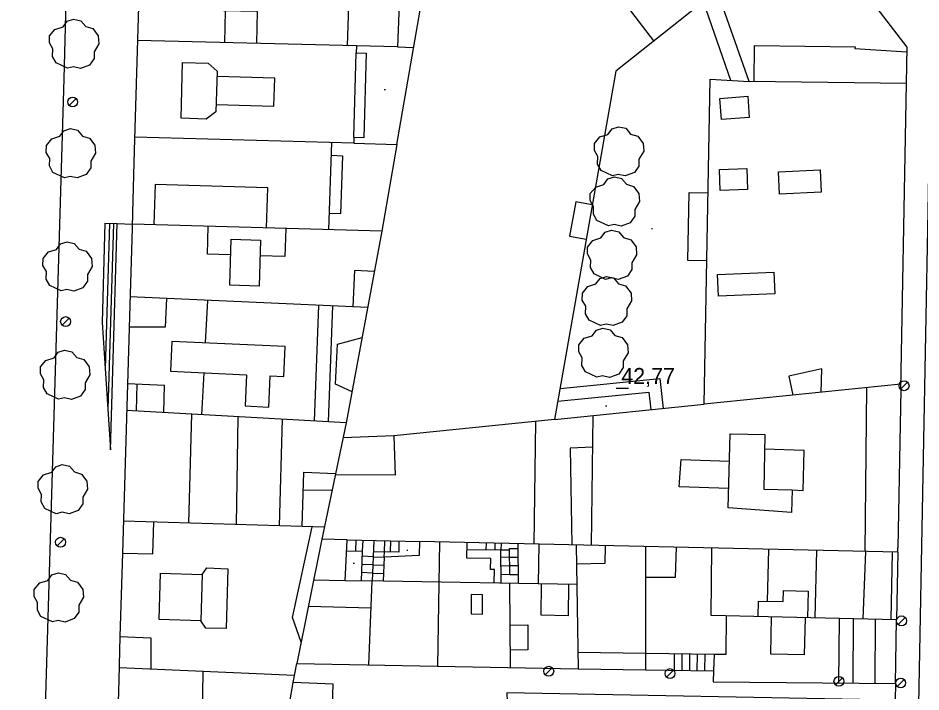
# Model space of a CAD drawing. Extents: x 431390 to 432653, y 4586754 to 4589600.
# Drawn here: x 431558.1 to 431631.4, y 4586887.9 to 4586942.6 of the extents above; entities that cross this region are included whole.
import ezdxf

# ---------------------------------------------------------------- set-up
doc = ezdxf.new("R2010")
doc.units = 0
for name, color, linetype in [('COM_13ES_LN', 7, 'Continuous'), ('COM_17LS_LN', 7, 'Continuous'), ('CON_01_LN', 7, 'Continuous'), ('CON_01FI_LN', 7, 'Continuous'), ('CON_03_LN', 7, 'Continuous'), ('CON_04_LN', 7, 'Continuous'), ('CON_07_LN', 7, 'Continuous'), ('CON_08_LN', 7, 'Continuous'), ('CON_15_LN', 7, 'Continuous'), ('CON_16_LN', 7, 'Continuous'), ('CON_19_LN', 7, 'Continuous'), ('CON_23_LN', 7, 'Continuous'), ('CON_29_LN', 7, 'Continuous'), ('ENE_06_PT', 7, 'Continuous'), ('ENE_08_LN', 7, 'Continuous'), ('ORO_03_PT', 7, 'Continuous'), ('ORO_04_PT', 7, 'Continuous'), ('ORO_04_TX', 7, 'Continuous'), ('VEG_03_PT', 7, 'Continuous')]:
    doc.layers.add(name, color=color, linetype=linetype)

msp = doc.modelspace()

# ---------------------------------------------------------------- linework, layer by layer
at = {"layer": 'COM_13ES_LN'}
for points in [[(431602.09, 4586912.527), (431610.17, 4586913.33), (431610.443, 4586910.91)], [(431601.911, 4586911.504), (431609.287, 4586912.237), (431609.448, 4586910.809)]]:
    msp.add_lwpolyline(points, dxfattribs=at)
at = {"layer": 'COM_17LS_LN'}
for points in [[(431557.318, 4586855.51), (431557.323, 4586855.702), (431559.44, 4586855.68), (431561.861, 4586937.649), (431562.206, 4586950.278), (431562.892, 4586975.427), (431562.96, 4586977.917), (431562.964, 4586978.068), (431563.607, 4587001.597), (431564.129, 4587020.727), (431564.211, 4587023.718), (431562.021, 4587023.778), (431562.213, 4587030.81)], [(431638.056, 4586933.587), (431637.559, 4586906.789), (431637.134, 4586883.917), (431636.702, 4586860.64), (431636.688, 4586859.878), (431630.69, 4586859.99), (431630.704, 4586860.75), (431631.136, 4586884.029), (431631.561, 4586906.901), (431631.932, 4586926.91), (431632.154, 4586938.86), (431632.209, 4586941.8), (431632.22, 4586942.4), (431632.187, 4586942.896)]]:
    msp.add_lwpolyline(points, dxfattribs=at)
at = {"layer": 'CON_01_LN'}
for points in [[(431606.16, 4586969.34), (431584.53, 4586970.044), (431569.734, 4586970.525), (431568.703, 4586970.559), (431568.404, 4586960.429), (431568.304, 4586957.039), (431567.56, 4586931.837), (431567.411, 4586926.808), (431567.374, 4586925.539), (431567.216, 4586920.177), (431566.596, 4586899.166)], [(431629.72, 4586912.441), (431630.23, 4586940.21), (431607.896, 4586969.283)], [(431629.72, 4586912.441), (431629.485, 4586899.612)], [(431629.478, 4586899.241), (431629.485, 4586899.612)], [(431566.596, 4586899.166), (431566.396, 4586892.411)], [(431629.478, 4586899.241), (431629.378, 4586893.771)], [(431629.283, 4586888.601), (431629.378, 4586893.771)], [(431566.396, 4586892.411), (431566.293, 4586888.909)], [(431566.293, 4586888.909), (431565.271, 4586854.269), (431571.972, 4586854.071)]]:
    msp.add_lwpolyline(points, dxfattribs=at)
at = {"layer": 'CON_01FI_LN'}
for points in [[(431585.553, 4586939.762), (431586.359, 4586939.74), (431586.172, 4586932.863), (431585.366, 4586932.885), (431585.354, 4586932.427), (431588.856, 4586932.332), (431591.761, 4586949.172), (431589.269, 4586949.253), (431588.9, 4586940.23), (431585.568, 4586940.313), (431585.553, 4586939.762)], [(431613.786, 4586911.25), (431614.26, 4586937.62), (431617.43, 4586937.44), (431614.833, 4586944.807), (431606.6, 4586938.27), (431601.65, 4586910.016), (431613.786, 4586911.25)], [(431590.691, 4586900.116), (431590.67, 4586898.99), (431587.829, 4586898.844), (431587.75, 4586896.886), (431584.667, 4586896.934), (431584.823, 4586900.249), (431590.691, 4586900.116)], [(431629.258, 4586887.249), (431597.76, 4586887.85), (431597.82, 4586886.43), (431583.634, 4586886.883), (431583.69, 4586888.54), (431580.455, 4586888.677), (431580.737, 4586890.231), (431603.548, 4586889.792), (431614.538, 4586889.618), (431614.51, 4586888.74), (431629.283, 4586888.601)]]:
    msp.add_lwpolyline(points, dxfattribs=at)
at = {"layer": 'CON_03_LN'}
for points in [[(431585.568, 4586940.313), (431567.823, 4586940.757)], [(431585.354, 4586932.427), (431567.592, 4586932.91)], [(431588.856, 4586932.332), (431587.64, 4586925.28), (431584.75, 4586909.73), (431582.74, 4586900.16), (431580.737, 4586890.231)], [(431587.64, 4586925.28), (431567.384, 4586925.869)], [(431586.49, 4586919.094), (431567.21, 4586919.959)], [(431629.728, 4586912.87), (431613.786, 4586911.25)], [(431584.75, 4586909.73), (431566.938, 4586910.754)], [(431601.65, 4586910.016), (431588.6, 4586908.69), (431584.498, 4586908.53)], [(431582.978, 4586901.291), (431566.673, 4586901.762)], [(431584.823, 4586900.249), (431582.768, 4586900.295)], [(431629.478, 4586899.241), (431590.691, 4586900.116)], [(431592.179, 4586890.011), (431592.33, 4586900.079)], [(431603.383, 4586899.83), (431603.548, 4586889.792)], [(431609.038, 4586889.705), (431609.044, 4586899.702)], [(431629.378, 4586893.771), (431614.35, 4586894.11), (431614.391, 4586899.581)], [(431586.577, 4586890.119), (431586.85, 4586896.9)], [(431598.061, 4586889.898), (431598.013, 4586896.726)], [(431615.547, 4586894.083), (431615.52, 4586890.96), (431614.58, 4586890.96), (431614.538, 4586889.618)], [(431580.559, 4586889.248), (431566.322, 4586889.88)], [(431574.158, 4586854.006), (431574.46, 4586872.98), (431575.4, 4586875.46), (431578.98, 4586875.44), (431580.51, 4586877.28), (431580.65, 4586883.4), (431579.55, 4586883.49), (431580.455, 4586888.677)]]:
    msp.add_lwpolyline(points, dxfattribs=at)
at = {"layer": 'CON_04_LN'}
for points in [[(431609.685, 4586940.72), (431598.38, 4586955.48), (431592.856, 4586955.684)], [(431577.492, 4586940.515), (431577.557, 4586943.1), (431574.807, 4586943.169), (431574.896, 4586946.709), (431577.66, 4586946.64), (431577.735, 4586949.629)], [(431584.841, 4586940.331), (431585.159, 4586949.387)], [(431574.897, 4586940.58), (431574.962, 4586943.165)], [(431585.366, 4586932.885), (431585.553, 4586939.762)], [(431571.482, 4586938.971), (431573.548, 4586938.909), (431574.28, 4586938.262), (431574.183, 4586934.971), (431573.389, 4586934.388), (431571.349, 4586934.448), (431571.482, 4586938.971)], [(431574.2, 4586935.557), (431578.883, 4586935.419), (431578.95, 4586937.706), (431574.268, 4586937.844)], [(431630.176, 4586937.27), (431617.43, 4586937.44)], [(431583.348, 4586925.405), (431583.582, 4586932.475)], [(431583.548, 4586931.443), (431584.447, 4586931.413), (431584.292, 4586926.695), (431583.392, 4586926.725)], [(431578.289, 4586925.552), (431578.384, 4586928.813), (431569.25, 4586929.079), (431569.155, 4586925.818)], [(431604.702, 4586927.439), (431603.356, 4586927.675), (431602.866, 4586924.876), (431604.212, 4586924.64)], [(431575.373, 4586923.366), (431573.49, 4586923.421), (431573.556, 4586925.69)], [(431579.843, 4586925.507), (431579.777, 4586923.238), (431577.747, 4586923.297)], [(431577.784, 4586924.57), (431577.675, 4586920.829), (431575.301, 4586920.898), (431575.41, 4586924.639), (431577.784, 4586924.57)], [(431587.036, 4586922.028), (431585.41, 4586922.1), (431585.272, 4586919.149)], [(431570.168, 4586919.826), (431570.06, 4586917.5), (431567.137, 4586917.503)], [(431573.347, 4586916.221), (431573.531, 4586919.675)], [(431582.166, 4586909.879), (431582.514, 4586919.272)], [(431583.296, 4586909.814), (431583.655, 4586919.221)], [(431570.49, 4586913.923), (431576.663, 4586913.65), (431576.551, 4586911.112), (431578.479, 4586911.027), (431578.59, 4586913.544), (431579.685, 4586913.496), (431579.793, 4586915.936), (431570.597, 4586916.343), (431570.49, 4586913.923)], [(431585.221, 4586912.263), (431583.89, 4586912.87), (431584.05, 4586916.12), (431586.04, 4586916.671)], [(431573.036, 4586910.403), (431573.217, 4586913.802)], [(431623.252, 4586912.212), (431623.33, 4586914.12), (431620.65, 4586913.54), (431620.957, 4586911.979)], [(431569.963, 4586910.58), (431570.01, 4586912.77), (431567.002, 4586912.912)], [(431567.776, 4586912.875), (431567.72, 4586910.709)], [(431626.842, 4586899.3), (431626.958, 4586912.589)], [(431575.946, 4586910.236), (431575.808, 4586901.498)], [(431599.991, 4586899.906), (431600.115, 4586909.86)], [(431604.631, 4586899.802), (431604.786, 4586910.335)], [(431588.6, 4586908.69), (431588.71, 4586905.51), (431583.864, 4586905.512)], [(431615.73, 4586902.841), (431615.87, 4586908.85), (431618.707, 4586908.784), (431618.604, 4586904.37), (431620.901, 4586904.317), (431620.858, 4586902.458), (431615.73, 4586902.841)], [(431604.748, 4586907.76), (431602.92, 4586907.7), (431603.047, 4586899.837)], [(431620.901, 4586904.317), (431621.81, 4586904.25), (431621.89, 4586907.5), (431618.68, 4586907.608)], [(431615.767, 4586904.422), (431611.74, 4586904.56), (431611.92, 4586906.76), (431615.818, 4586906.633)], [(431581.171, 4586901.343), (431581.32, 4586905.73), (431583.887, 4586905.621)], [(431583.597, 4586904.242), (431581.271, 4586904.283)], [(431566.596, 4586899.166), (431569.05, 4586899.13), (431569.151, 4586901.69)], [(431581.083, 4586891.945), (431580.4, 4586893.96), (431581.981, 4586901.32)], [(431596.755, 4586896.745), (431596.772, 4586897.839), (431596.458, 4586897.844), (431596.472, 4586898.725), (431594.525, 4586898.755), (431594.545, 4586900.029)], [(431598.713, 4586896.715), (431598.69, 4586899.936)], [(431600.352, 4586896.689), (431600.402, 4586899.897)], [(431605.754, 4586899.776), (431605.72, 4586898.32), (431603.408, 4586898.29)], [(431611.493, 4586899.647), (431611.41, 4586897.21), (431609.042, 4586897.2)], [(431597.313, 4586896.737), (431597.294, 4586899.421), (431594.536, 4586899.451)], [(431618.917, 4586895.272), (431619.012, 4586899.477)], [(431622.765, 4586893.92), (431622.904, 4586899.389)], [(431626.657, 4586893.832), (431626.876, 4586899.3)], [(431628.935, 4586893.781), (431629.04, 4586899.251)], [(431573.062, 4586897.439), (431573.44, 4586897.98), (431575.15, 4586897.89), (431575, 4586893.05), (431573.36, 4586893.1), (431572.954, 4586893.693), (431569.58, 4586893.79), (431569.688, 4586897.536), (431573.062, 4586897.439), (431572.954, 4586893.693)], [(431584.667, 4586896.934), (431582.097, 4586896.974)], [(431603.435, 4586896.641), (431587.75, 4586896.886)], [(431602.78, 4586896.651), (431602.74, 4586894.1), (431600.544, 4586894.135), (431600.584, 4586896.686)], [(431618.162, 4586894.024), (431618.191, 4586895.288), (431620.175, 4586895.243), (431620.195, 4586896.135), (431622.203, 4586896.09), (431622.154, 4586893.934)], [(431594.867, 4586894.247), (431595.785, 4586894.233), (431595.808, 4586895.793), (431594.89, 4586895.807), (431594.867, 4586894.247)], [(431586.762, 4586894.705), (431581.667, 4586894.843)], [(431621.964, 4586893.938), (431621.896, 4586890.92), (431619.179, 4586890.981), (431619.247, 4586894)], [(431624.69, 4586888.644), (431624.739, 4586893.876)], [(431625.849, 4586888.633), (431625.898, 4586893.85)], [(431627.63, 4586888.617), (431627.679, 4586893.809)], [(431598.037, 4586893.335), (431599.473, 4586893.345), (431599.487, 4586891.323), (431598.051, 4586891.313)], [(431566.396, 4586892.411), (431568.91, 4586892.29), (431568.892, 4586889.766)], [(431614.58, 4586890.96), (431603.526, 4586891.102)], [(431572.862, 4586871.352), (431573.151, 4586889.577)]]:
    msp.add_lwpolyline(points, dxfattribs=at)
at = {"layer": 'CON_07_LN'}
msp.add_lwpolyline([(431613.995, 4586922.889), (431612.453, 4586922.917), (431612.552, 4586928.422), (431614.094, 4586928.394)], dxfattribs=at)
at = {"layer": 'CON_08_LN'}
msp.add_lwpolyline([(431613.705, 4586943.911), (431615.915, 4586937.526)], dxfattribs=at)
at = {"layer": 'CON_15_LN'}
msp.add_lwpolyline([(431565.184, 4586925.933), (431566.184, 4586925.904), (431567.384, 4586925.869)], dxfattribs=at)
at = {"layer": 'CON_16_LN'}
for points in [[(431588.9, 4586940.23), (431590.209, 4586940.177)], [(431598.008, 4586897.429), (431597.993, 4586899.54)]]:
    msp.add_lwpolyline(points, dxfattribs=at)
at = {"layer": 'CON_19_LN'}
msp.add_lwpolyline([(431629.283, 4586888.601), (431629.258, 4586887.249)], dxfattribs=at)
at = {"layer": 'CON_23_LN'}
for points in [[(431565.184, 4586925.933), (431564.947, 4586917.873), (431565.197, 4586914.156), (431565.42, 4586910.849), (431565.643, 4586907.541), (431566.184, 4586925.904)], [(431565.544, 4586925.923), (431565.197, 4586914.156)], [(431565.864, 4586925.913), (431565.42, 4586910.849)], [(431585.513, 4586900.233), (431585.492, 4586899.334)], [(431586.083, 4586900.22), (431586.047, 4586899.321)], [(431586.983, 4586900.2), (431586.85, 4586896.9)], [(431587.846, 4586899.28), (431587.883, 4586900.18)], [(431589.023, 4586900.154), (431589.003, 4586899.254), (431587.846, 4586899.28)], [(431588.343, 4586900.169), (431588.323, 4586899.269)], [(431596.082, 4586899.994), (431596.069, 4586899.433)], [(431596.802, 4586899.978), (431596.79, 4586899.426)], [(431597.306, 4586899.967), (431597.294, 4586899.421)], [(431597.993, 4586899.54), (431598.693, 4586899.545)], [(431584.781, 4586899.35), (431586.047, 4586899.321)], [(431586.047, 4586899.321), (431585.95, 4586896.914)], [(431586.93, 4586898.88), (431586.031, 4586898.916)], [(431586.93, 4586898.88), (431587.829, 4586898.844)], [(431586.947, 4586899.3), (431587.846, 4586899.28)], [(431587.829, 4586898.844), (431587.846, 4586899.28)], [(431597.994, 4586899.426), (431597.294, 4586899.421)], [(431597.998, 4586898.837), (431597.298, 4586898.832)], [(431597.998, 4586898.836), (431598.698, 4586898.841)], [(431586.903, 4586898.22), (431586.004, 4586898.256)], [(431586.903, 4586898.22), (431587.802, 4586898.184)], [(431598.703, 4586898.138), (431598.003, 4586898.133), (431597.303, 4586898.128)], [(431586.877, 4586897.56), (431585.977, 4586897.596)], [(431586.877, 4586897.56), (431587.776, 4586897.524)], [(431598.008, 4586897.43), (431597.308, 4586897.425)], [(431598.008, 4586897.429), (431598.708, 4586897.434)], [(431611.348, 4586891.002), (431611.331, 4586889.669)], [(431611.969, 4586890.994), (431611.952, 4586889.659)], [(431612.59, 4586890.986), (431612.573, 4586889.649)], [(431613.21, 4586890.978), (431613.193, 4586889.639)], [(431613.831, 4586890.97), (431613.814, 4586889.629)]]:
    msp.add_lwpolyline(points, dxfattribs=at)
at = {"layer": 'CON_29_LN'}
for points in [[(431572.195, 4586910.452), (431571.949, 4586901.61)], [(431579.543, 4586910.029), (431579.318, 4586901.397)]]:
    msp.add_lwpolyline(points, dxfattribs=at)
at = {"layer": 'ENE_06_PT'}
for p, q in [((431562.842, 4586936.052), (431562.276, 4586935.486)), ((431562.272, 4586918.242), (431561.706, 4586917.676)), ((431630.272, 4586913.032), (431629.706, 4586912.466)), ((431561.862, 4586900.342), (431561.296, 4586899.776)), ((431630.062, 4586893.962), (431629.496, 4586893.396)), ((431601.455, 4586889.876), (431600.889, 4586889.31)), ((431611.287, 4586889.686), (431610.721, 4586889.12)), ((431624.984, 4586889.052), (431624.418, 4586888.486)), ((431629.991, 4586888.922), (431629.425, 4586888.356))]:
    msp.add_line(p, q, dxfattribs=at)
for centre in [(431562.559, 4586935.769), (431561.989, 4586917.959), (431629.989, 4586912.749), (431561.579, 4586900.059), (431629.779, 4586893.679), (431601.172, 4586889.593), (431611.004, 4586889.403), (431624.701, 4586888.769), (431629.708, 4586888.639)]:
    msp.add_circle(centre, 0.4, dxfattribs=at)
at = {"layer": 'ENE_08_LN'}
for points in [[(431617.829, 4586937.435), (431617.869, 4586940.342), (431626.01, 4586940.23), (431626.002, 4586940.1), (431630.223, 4586939.838)], [(431617.434, 4586934.503), (431615.18, 4586934.34), (431615.055, 4586936.065), (431617.309, 4586936.228), (431617.434, 4586934.503)], [(431617.294, 4586928.661), (431615.08, 4586928.59), (431615.025, 4586930.299), (431617.239, 4586930.37), (431617.294, 4586928.661)], [(431623.255, 4586928.463), (431619.88, 4586928.3), (431619.793, 4586930.102), (431623.168, 4586930.265), (431623.255, 4586928.463)], [(431619.506, 4586920.21), (431614.93, 4586920.01), (431614.853, 4586921.764), (431619.429, 4586921.964), (431619.506, 4586920.21)]]:
    msp.add_lwpolyline(points, dxfattribs=at)
at = {"layer": 'ORO_03_PT'}
for p, q in [((431587.83, 4586936.79), (431587.93, 4586936.79)), ((431609.49, 4586925.5), (431609.59, 4586925.5)), ((431605.78, 4586911.11), (431605.88, 4586911.11)), ((431589.65, 4586899.42), (431589.75, 4586899.42)), ((431585.31, 4586898.35), (431585.41, 4586898.35))]:
    msp.add_line(p, q, dxfattribs=at)
at = {"layer": 'ORO_04_PT'}
msp.add_line((431606.63, 4586912.55), (431607.63, 4586912.55), dxfattribs=at)
at = {"layer": 'VEG_03_PT'}
for points in [[(431562.154, 4586938.501), (431561.227, 4586938.936), (431560.939, 4586939.457), (431560.962, 4586940.071), (431560.68, 4586940.563), (431560.688, 4586941.126), (431561.129, 4586941.661), (431561.782, 4586941.865), (431562.117, 4586942.316), (431562.643, 4586942.486), (431563.223, 4586942.353), (431563.623, 4586941.887), (431564.197, 4586941.717), (431564.631, 4586941.134), (431564.68, 4586940.492), (431564.297, 4586939.845), (431564.297, 4586939.295), (431563.925, 4586938.761), (431563.186, 4586938.486), (431562.621, 4586938.614), (431562.154, 4586938.501)], [(431561.894, 4586929.621), (431560.967, 4586930.056), (431560.679, 4586930.577), (431560.702, 4586931.191), (431560.42, 4586931.683), (431560.428, 4586932.246), (431560.869, 4586932.781), (431561.522, 4586932.985), (431561.857, 4586933.436), (431562.383, 4586933.606), (431562.963, 4586933.473), (431563.363, 4586933.007), (431563.937, 4586932.837), (431564.371, 4586932.254), (431564.42, 4586931.612), (431564.037, 4586930.965), (431564.037, 4586930.415), (431563.665, 4586929.881), (431562.926, 4586929.606), (431562.361, 4586929.734), (431561.894, 4586929.621)], [(431606.344, 4586929.781), (431605.417, 4586930.216), (431605.129, 4586930.737), (431605.152, 4586931.351), (431604.87, 4586931.843), (431604.878, 4586932.406), (431605.319, 4586932.941), (431605.972, 4586933.145), (431606.307, 4586933.596), (431606.833, 4586933.766), (431607.413, 4586933.633), (431607.813, 4586933.167), (431608.387, 4586932.997), (431608.821, 4586932.414), (431608.87, 4586931.772), (431608.487, 4586931.125), (431608.487, 4586930.575), (431608.115, 4586930.041), (431607.376, 4586929.766), (431606.811, 4586929.894), (431606.344, 4586929.781)], [(431606.004, 4586925.711), (431605.077, 4586926.146), (431604.789, 4586926.667), (431604.812, 4586927.281), (431604.53, 4586927.773), (431604.538, 4586928.336), (431604.979, 4586928.871), (431605.632, 4586929.075), (431605.967, 4586929.526), (431606.493, 4586929.696), (431607.073, 4586929.563), (431607.473, 4586929.097), (431608.047, 4586928.927), (431608.481, 4586928.344), (431608.53, 4586927.702), (431608.147, 4586927.055), (431608.147, 4586926.505), (431607.775, 4586925.971), (431607.036, 4586925.696), (431606.471, 4586925.824), (431606.004, 4586925.711)], [(431605.774, 4586921.381), (431604.847, 4586921.816), (431604.559, 4586922.337), (431604.582, 4586922.951), (431604.3, 4586923.443), (431604.308, 4586924.006), (431604.749, 4586924.541), (431605.402, 4586924.745), (431605.737, 4586925.196), (431606.263, 4586925.366), (431606.843, 4586925.233), (431607.243, 4586924.767), (431607.817, 4586924.597), (431608.251, 4586924.014), (431608.3, 4586923.372), (431607.917, 4586922.725), (431607.917, 4586922.175), (431607.545, 4586921.641), (431606.806, 4586921.366), (431606.241, 4586921.494), (431605.774, 4586921.381)], [(431561.624, 4586920.441), (431560.697, 4586920.876), (431560.409, 4586921.397), (431560.432, 4586922.011), (431560.15, 4586922.503), (431560.158, 4586923.066), (431560.599, 4586923.601), (431561.252, 4586923.805), (431561.587, 4586924.256), (431562.113, 4586924.426), (431562.693, 4586924.293), (431563.093, 4586923.827), (431563.667, 4586923.657), (431564.101, 4586923.074), (431564.15, 4586922.432), (431563.767, 4586921.785), (431563.767, 4586921.235), (431563.395, 4586920.701), (431562.656, 4586920.426), (431562.091, 4586920.554), (431561.624, 4586920.441)], [(431605.364, 4586917.641), (431604.437, 4586918.076), (431604.149, 4586918.597), (431604.172, 4586919.211), (431603.89, 4586919.703), (431603.898, 4586920.266), (431604.339, 4586920.801), (431604.992, 4586921.005), (431605.327, 4586921.456), (431605.853, 4586921.626), (431606.433, 4586921.493), (431606.833, 4586921.027), (431607.407, 4586920.857), (431607.841, 4586920.274), (431607.89, 4586919.632), (431607.507, 4586918.985), (431607.507, 4586918.435), (431607.135, 4586917.901), (431606.396, 4586917.626), (431605.831, 4586917.754), (431605.364, 4586917.641)], [(431605.074, 4586913.441), (431604.147, 4586913.876), (431603.859, 4586914.397), (431603.882, 4586915.011), (431603.6, 4586915.503), (431603.608, 4586916.066), (431604.049, 4586916.601), (431604.702, 4586916.805), (431605.037, 4586917.256), (431605.563, 4586917.426), (431606.143, 4586917.293), (431606.543, 4586916.827), (431607.117, 4586916.657), (431607.551, 4586916.074), (431607.6, 4586915.432), (431607.217, 4586914.785), (431607.217, 4586914.235), (431606.845, 4586913.701), (431606.106, 4586913.426), (431605.541, 4586913.554), (431605.074, 4586913.441)], [(431561.424, 4586911.651), (431560.497, 4586912.086), (431560.209, 4586912.607), (431560.232, 4586913.221), (431559.95, 4586913.713), (431559.958, 4586914.276), (431560.399, 4586914.811), (431561.052, 4586915.015), (431561.387, 4586915.466), (431561.913, 4586915.636), (431562.493, 4586915.503), (431562.893, 4586915.037), (431563.467, 4586914.867), (431563.901, 4586914.284), (431563.95, 4586913.642), (431563.567, 4586912.995), (431563.567, 4586912.445), (431563.195, 4586911.911), (431562.456, 4586911.636), (431561.891, 4586911.764), (431561.424, 4586911.651)], [(431561.234, 4586902.371), (431560.307, 4586902.806), (431560.019, 4586903.327), (431560.042, 4586903.941), (431559.76, 4586904.433), (431559.768, 4586904.996), (431560.209, 4586905.531), (431560.862, 4586905.735), (431561.197, 4586906.186), (431561.723, 4586906.356), (431562.303, 4586906.223), (431562.703, 4586905.757), (431563.277, 4586905.587), (431563.711, 4586905.004), (431563.76, 4586904.362), (431563.377, 4586903.715), (431563.377, 4586903.165), (431563.005, 4586902.631), (431562.266, 4586902.356), (431561.701, 4586902.484), (431561.234, 4586902.371)], [(431560.914, 4586893.601), (431559.987, 4586894.036), (431559.699, 4586894.557), (431559.722, 4586895.171), (431559.44, 4586895.663), (431559.448, 4586896.226), (431559.889, 4586896.761), (431560.542, 4586896.965), (431560.877, 4586897.416), (431561.403, 4586897.586), (431561.983, 4586897.453), (431562.383, 4586896.987), (431562.957, 4586896.817), (431563.391, 4586896.234), (431563.44, 4586895.592), (431563.057, 4586894.945), (431563.057, 4586894.395), (431562.685, 4586893.861), (431561.946, 4586893.586), (431561.381, 4586893.714), (431560.914, 4586893.601)]]:
    msp.add_lwpolyline(points, dxfattribs=at)

# ---------------------------------------------------------------- texts
at = {"layer": 'ORO_04_TX'}
msp.add_text('42,77', height=1.3, dxfattribs=at).set_placement((431607.053, 4586912.891))

doc.saveas('drawing.dxf')
